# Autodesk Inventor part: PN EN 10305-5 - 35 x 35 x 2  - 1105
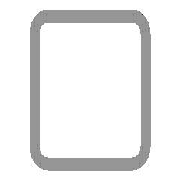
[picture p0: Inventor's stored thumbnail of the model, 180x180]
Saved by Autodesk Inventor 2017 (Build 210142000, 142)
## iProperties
_CCFamilyMember: 22
_CCFamilyDisplayName: PN EN 10305-5 (Rury kwadratowe, spawane, wymiarowane na zimno) - Rury stalowe do zastosowań precyzyjnych -  (Część 5: Rury kwadratowe, spawane, wymiarowane na z
_FrameMemberDoc: Frame Member File
_Version: 15.0.0
_GetPNFromCC: 1
Created: 2016-02
Part Number: PN EN 10305-5 - 35 x 35 x 2  - 1105
Material: Stal, miękka
Description: Rury stalowe do zastosowań precyzyjnych -  (Część 5: Rury kwadratowe, spawane, wymiarowane na zimno)
Document SubType Name: Modeling
Standard: PN
Designer: X
Standards Organization: PN
Language: pl-PL
Size Designation: 35 x 35 x 2
Categories: <MemberInstance><Categories><Category DisplayName="Kształtowniki konstrukcyjne" InternalName="089c4875-fa83-4c05-b084-43b9cc11f5ed" Mnemonic="GRDR"><CategoryPar
Stock Number: 35 x 35 x 2
Density: 7.85 g/cm^3
Appearance: Częściowo polerowana
IsCustomPart: 1
G_L: 1105,000 mm
G_W: 35,000 mm
G_H: 35,000 mm
Author: X
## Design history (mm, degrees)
node "Płaszczyzna początkowa"
node "Płaszczyzna końcowa"
sketch "Szkic"
  geometry: L1 (-17.5, -14.5)-(-17.5, 14.5); L2 (-14.5, 17.5)-(14.5, 17.5); L3 (17.5, 14.5)-(17.5, -14.5); L4 (14.5, -17.5)-(-14.5, -17.5); L5 (-14.5, 15.5)-(14.5, 15.5); L6 (15.5, 14.5)-(15.5, -14.5); L7 (14.5, -15.5)-(-14.5, -15.5); L8 (-15.5, -14.5)-(-15.5, 14.5); L9 (0, 25.37)-(0, -25.37) reference; L10 (-25.37, 0)-(25.37, 0) reference; A1 r 3 centre (-14.5, -14.5) between (-17.5, -14.5) and (-14.5, -17.5); A2 r 3 centre (-14.5, 14.5) between (-14.5, 17.5) and (-17.5, 14.5); A3 r 3 centre (14.5, 14.5) between (17.5, 14.5) and (14.5, 17.5); A4 r 3 centre (14.5, -14.5) between (14.5, -17.5) and (17.5, -14.5); A5 r 1 centre (-14.5, 14.5) between (-14.5, 15.5) and (-15.5, 14.5); A6 r 1 centre (14.5, 14.5) between (15.5, 14.5) and (14.5, 15.5); A7 r 1 centre (14.5, -14.5) between (14.5, -15.5) and (15.5, -14.5); A8 r 1 centre (-14.5, -14.5) between (-15.5, -14.5) and (-14.5, -15.5)
  constraints: 16 end point, 16 point on circle, 8 centre point, 8 tangent, 4 parallel, 3 equal radius, 2 perpendicular, 7 other
  dimensions: "d7" = 3 radius of A1 (= G_IR); "d10" = 35 distance between parallel lines of L2 L4 (= G_H); "d11" = 35 distance between parallel lines of L1 L3 (= G_W); "d12" = 2 distance between parallel lines of L3 L6 (= G_T); "d15" = 17.5 distance between parallel lines of L2 L10 (= 0.5 x d10); "d16" = 17.5 distance between parallel lines of L9 L3 (= 0.5 x d11)
extrude "Bryła" new body sketch "Szkic" stored distance "d3" = 1105 (= G_L); taper "d4" = 0 deg
node "Driven Length"
  sketch "Sketch3"
    geometry: L1 (0, 0)-(10, 0) reference
    constraints: 2 end point, 1 horizontal
  workplane "Work Plane3"
  sketch "Sketch4"
    geometry: L1 (-2, 0)-(12, 0) reference; L2 (-2, 1105)-(12, 1105) reference
    dimensions: "d18" = 1105 distance between parallel lines of L1 L2 (derived)
body "Solid1"
other parameters: "G_W" = 35 [user parameter; used in 1 equation term], "G_H" = 35 [user parameter; used in 1 equation term], "G_T" = 2 [user parameter; used in 1 equation term], "G_IR" = 3 [user parameter; used in 1 equation term], "G_L" = 1105 (= d18) [user parameter; used in 1 equation term], "G_OFFSET_START" = 0 [user parameter; used in 1 equation term], "G_OFFSET_END" = -35 [user parameter; used in 1 equation term], "d13" = 0 (computed from G_OFFSET_START), "d14" = 1105 (= G_OFFSET_END + B_L), "d17" = 90 deg
